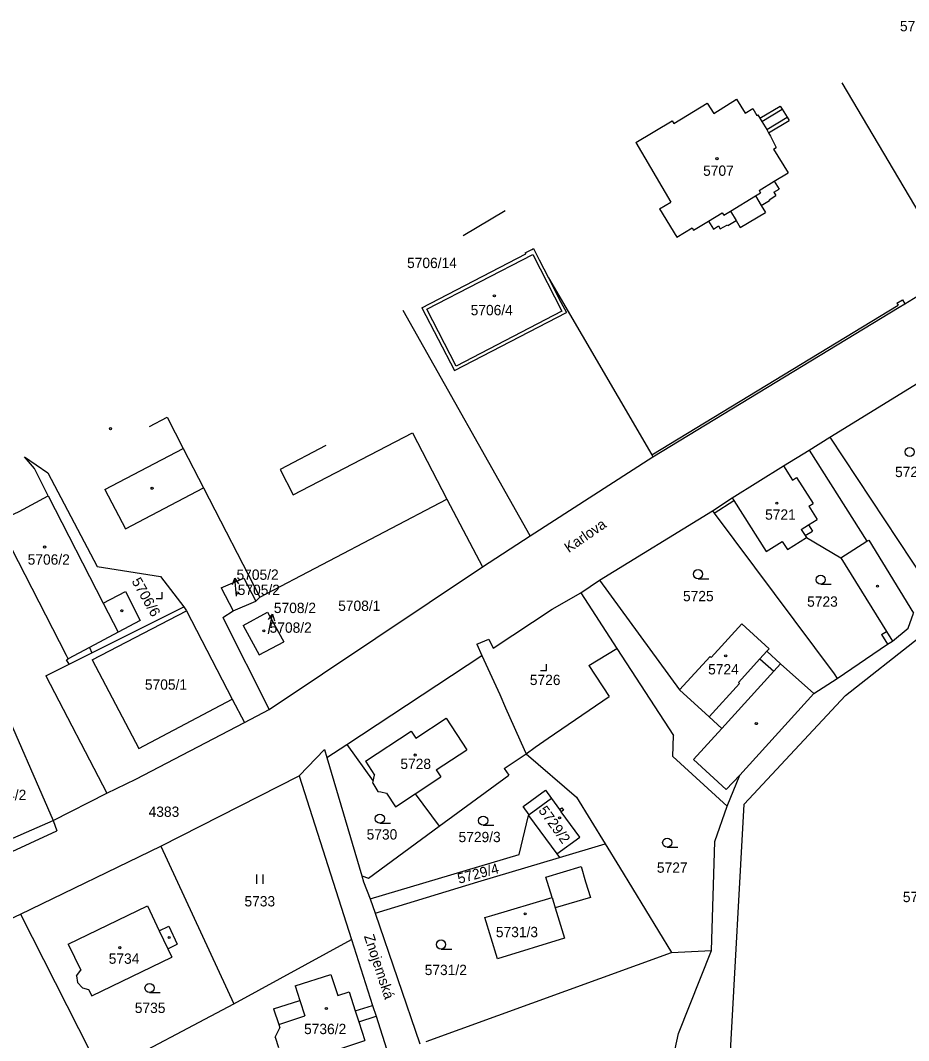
# Model space of a CAD drawing. Extents: x -717507 to -715515, y -957700 to -954941.
# Drawn here: x -716123.2 to -715976.7, y -955263.6 to -955095.4 of the extents above; entities that cross this region are included whole.
import ezdxf

# ---------------------------------------------------------------- set-up
doc = ezdxf.new("R2010")
doc.units = 0
for name, color, linetype in [('Hranice parcel', 7, 'Continuous'), ('Parcelní čísla', 7, 'Continuous'), ('Pop  PČ popisy', 7, 'Continuous'), ('Vnitřní kresba', 7, 'Continuous'), ('Značky budov', 7, 'Continuous'), ('Značky kultur', 7, 'Continuous')]:
    doc.layers.add(name, color=color, linetype=linetype)

msp = doc.modelspace()

# ---------------------------------------------------------------- linework, layer by layer
at = {"layer": 'Hranice parcel'}
for points in [[(-715987.69, -955105.68), (-715972.32, -955131.55)], [(-716008.8, -955110.73), (-716005.06, -955108.37)], [(-716005.06, -955108.37), (-716003.64, -955110.67)], [(-716015.41, -955112.35), (-716009.88, -955109.01)], [(-716009.88, -955109.01), (-716008.8, -955110.73)], [(-716003.64, -955110.67), (-716002.36, -955109.88)], [(-716002.36, -955109.88), (-716001.7, -955111.02)], [(-716001.2, -955111.49), (-715997.86, -955109.49)], [(-715997.86, -955109.49), (-715997.54, -955110)], [(-715997.54, -955110), (-715996.7, -955111.34)], [(-716001.7, -955111.02), (-716001.55, -955110.92)], [(-716001.55, -955110.92), (-716001.2, -955111.49)], [(-715999.76, -955113.88), (-715996.39, -955111.84)], [(-715996.7, -955111.34), (-715996.39, -955111.84)], [(-716021.63, -955115.52), (-716015.66, -955111.92)], [(-716015.66, -955111.92), (-716015.41, -955112.35)], [(-715999.76, -955113.88), (-715999.42, -955114.45)], [(-715999.42, -955114.45), (-715998.49, -955116.34)], [(-716021.63, -955115.52), (-716015.9, -955125.35)], [(-715998.93, -955116.6), (-715998.49, -955116.34)], [(-715998.93, -955116.6), (-715996.55, -955120.52)], [(-715998.82, -955121.89), (-715996.55, -955120.52)], [(-715998.82, -955121.89), (-715998.03, -955123.18)], [(-715998.87, -955123.7), (-715998.03, -955123.18)], [(-716000.97, -955125.87), (-715999.62, -955125.05)], [(-715999.69, -955124.94), (-715998.54, -955124.25)], [(-715999.69, -955124.94), (-715999.62, -955125.05)], [(-715998.87, -955123.7), (-715998.54, -955124.25)], [(-716050.13, -955130.83), (-716043.22, -955126.68)], [(-716017.73, -955126.42), (-716015.9, -955125.35)], [(-716017.73, -955126.42), (-716014.91, -955131.1)], [(-716000.97, -955125.87), (-716000.28, -955127.01)], [(-716012.15, -955129.96), (-716009.65, -955128.46)], [(-716009.65, -955128.46), (-716008.83, -955129.76)], [(-716006.48, -955129.17), (-716005.12, -955128.35)], [(-716005.12, -955128.35), (-716004.43, -955129.49)], [(-716004.43, -955129.49), (-716000.28, -955127.01)], [(-716014.91, -955131.1), (-716012.39, -955129.54)], [(-716012.39, -955129.54), (-716012.15, -955129.96)], [(-716008.83, -955129.76), (-716008.04, -955129.25)], [(-716008.04, -955129.25), (-716007.73, -955129.73)], [(-716007.73, -955129.73), (-716006.55, -955129.06)], [(-716006.55, -955129.06), (-716006.48, -955129.17)], [(-716039.91, -955133.7), (-716038.79, -955133.12)], [(-716039.91, -955133.7), (-716039.82, -955133.87)], [(-716038.79, -955133.12), (-716038.55, -955133)], [(-716038.55, -955133), (-716037.58, -955134.87)], [(-716056.93, -955142.74), (-716039.82, -955133.87)], [(-716037.58, -955134.87), (-716036.07, -955137.79)], [(-716036.07, -955137.79), (-716019.04, -955167.01)], [(-716036.07, -955137.79), (-716034, -955141.8)], [(-715977.3, -955142.09), (-715974.43, -955140.34)], [(-716034, -955141.8), (-716033.1, -955143.53)], [(-715978.21, -955142.64), (-715977.3, -955142.09)], [(-716039.06, -955180.37), (-716060.02, -955143.22)], [(-716056.93, -955142.74), (-716051.56, -955153.11)], [(-716051.56, -955153.11), (-716033.1, -955143.53)], [(-716018.86, -955167.31), (-715978.21, -955142.64)], [(-715989.65, -955164.11), (-715972.95, -955153.83)], [(-715993.06, -955166.21), (-715989.65, -955164.11)], [(-715989.65, -955164.11), (-715973.88, -955187.93)], [(-716120.85, -955169.23), (-716122.47, -955167.34)], [(-716122.47, -955167.34), (-716118.65, -955169.98)], [(-716039.06, -955180.37), (-716018.86, -955167.31)], [(-716019.04, -955167.01), (-716018.86, -955167.31)], [(-715997.31, -955168.83), (-715993.06, -955166.21)], [(-716005.75, -955174.07), (-715997.31, -955168.83)], [(-716118.59, -955173.74), (-716120.85, -955169.23)], [(-716118.65, -955169.98), (-716110.5, -955185.44)], [(-716126.97, -955178), (-716123.36, -955176.36), (-716118.59, -955173.74)], [(-716118.59, -955173.74), (-716109.53, -955191.45)], [(-716008.99, -955176.24), (-716005.75, -955174.07)], [(-716005.75, -955174.07), (-716005.48, -955174.51)], [(-716083.7, -955190.49), (-716052.81, -955174.31)], [(-716052.81, -955174.31), (-716046.97, -955185.48)], [(-716005.48, -955174.51), (-716000.17, -955182.94)], [(-716027.64, -955187.66), (-716008.99, -955176.24)], [(-716008.99, -955176.24), (-716008.72, -955176.6)], [(-716008.72, -955176.6), (-715988.93, -955203.13)], [(-716115.27, -955200.63), (-716115.56, -955200.09), (-716126.97, -955178)], [(-716046.97, -955185.48), (-716039.06, -955180.37)], [(-715996.66, -955182.61), (-715993.51, -955180.65)], [(-715993.51, -955180.65), (-715987.84, -955183.98)], [(-716000.17, -955182.94), (-715997.5, -955181.27)], [(-715997.5, -955181.27), (-715996.66, -955182.61)], [(-715987.84, -955183.98), (-715980.3, -955196.11)], [(-716110.5, -955185.44), (-716100.06, -955187.09)], [(-716082.16, -955209.02), (-716046.97, -955185.48)], [(-716100.06, -955187.09), (-716096.2, -955192.09)], [(-716090.05, -955188.92), (-716086.33, -955187.35)], [(-716086.33, -955187.35), (-716084.35, -955191.14)], [(-716090.05, -955188.92), (-716088.05, -955192.75)], [(-716030.73, -955189.77), (-716027.64, -955187.66)], [(-716027.64, -955187.66), (-716014.46, -955205.75)], [(-716109.53, -955191.45), (-716105.82, -955189.55), (-716103.41, -955194.34), (-716107.07, -955196.25)], [(-716084.35, -955191.14), (-716083.7, -955190.49)], [(-716035.48, -955192.46), (-716030.73, -955189.77)], [(-716030.73, -955189.77), (-716024.77, -955198.93)], [(-716111.37, -955199.63), (-716096.2, -955192.09)], [(-716096.2, -955192.09), (-716095.75, -955192.74)], [(-716088.05, -955192.75), (-716084.35, -955191.14)], [(-716045.19, -955198.88), (-716035.48, -955192.46)], [(-716095.75, -955192.74), (-716088.23, -955207.29)], [(-716089.76, -955193.81), (-716088.05, -955192.75)], [(-716089.76, -955193.81), (-716082.16, -955209.02)], [(-716086.41, -955195.12), (-716082.39, -955192.95)], [(-716082.39, -955192.95), (-716079.74, -955197.82)], [(-715976.75, -955195.61), (-715975.85, -955193.1)], [(-716086.41, -955195.12), (-716083.78, -955200)], [(-716009.23, -955200.42), (-716004.16, -955194.89)], [(-716004.16, -955194.89), (-715999.69, -955198.98)], [(-715979.32, -955197.7), (-715976.75, -955195.61)], [(-716107.07, -955196.25), (-716111.77, -955198.76)], [(-716047.89, -955198.2), (-716045.88, -955197.4)], [(-716045.88, -955197.4), (-716045.19, -955198.88)], [(-715987.09, -955206.67), (-715974.9, -955197.11)], [(-715981.14, -955196.63), (-715980.3, -955196.11)], [(-715981.14, -955196.63), (-715980.17, -955198.23)], [(-716111.77, -955198.76), (-716111.37, -955199.63)], [(-716083.78, -955200), (-716079.74, -955197.82)], [(-716047.89, -955198.2), (-716047.03, -955200.09)], [(-716029.43, -955201.72), (-716024.77, -955198.93)], [(-716024.77, -955198.93), (-716015.42, -955213.31)], [(-716000.06, -955199.39), (-715999.69, -955198.98)], [(-715988.45, -955203.88), (-715980.17, -955198.23)], [(-715980.17, -955198.23), (-715979.32, -955197.7)], [(-716115.14, -955201.51), (-716115.56, -955200.79), (-716115.27, -955200.63)], [(-716115.14, -955201.51), (-716111.37, -955199.63)], [(-716069.3, -955214.76), (-716047.03, -955200.09)], [(-716047.03, -955200.09), (-716044.1, -955206.54), (-716043.13, -955208.71), (-716040.06, -955215.58), (-716039.75, -955216.28)], [(-716014.46, -955205.75), (-716009.42, -955200.26)], [(-716009.42, -955200.26), (-716009.23, -955200.42)], [(-716000.06, -955199.39), (-715997.78, -955201.44)], [(-716118.98, -955203.42), (-716115.14, -955201.51)], [(-716029.43, -955201.72), (-716026.06, -955206.87)], [(-715997.78, -955201.44), (-715992.32, -955206.35)], [(-716118.98, -955203.42), (-716108.91, -955222.79)], [(-715992.32, -955206.35), (-715988.45, -955203.88)], [(-715988.93, -955203.13), (-715988.45, -955203.88)], [(-716126.78, -955206.75), (-716117.79, -955227.32)], [(-716088.23, -955207.29), (-716086.22, -955211.13)], [(-716036.1, -955213.7), (-716026.06, -955206.87)], [(-716004.49, -955219.83), (-715992.32, -955206.35)], [(-716003.78, -955224.58), (-715987.09, -955206.67)], [(-716086.22, -955211.13), (-716082.16, -955209.02)], [(-716104.15, -955220.46), (-716086.22, -955211.13)], [(-716038.28, -955215.18), (-716036.1, -955213.7)], [(-716015.54, -955216.77), (-716015.42, -955213.31)], [(-716077.16, -955219.93), (-716072.99, -955215.59)], [(-716072.99, -955215.59), (-716072.6, -955216.93)], [(-716072.6, -955216.93), (-716069.3, -955214.76)], [(-716069.3, -955214.76), (-716064.99, -955220.82)], [(-716039.75, -955216.28), (-716038.28, -955215.18)], [(-716072.6, -955216.93), (-716066.86, -955236.41)], [(-716043.36, -955218.75), (-716039.75, -955216.28)], [(-716039.75, -955216.28), (-716031.42, -955223.44)], [(-716015.54, -955216.77), (-716006.58, -955224.96)], [(-716043.36, -955218.75), (-716042.6, -955219.81)], [(-716108.91, -955222.79), (-716104.15, -955220.46)], [(-716100.02, -955231.55), (-716077.16, -955219.93)], [(-716077.16, -955219.93), (-716068.57, -955246.93)], [(-716065.06, -955221.15), (-716064.99, -955220.82)], [(-716065.06, -955221.15), (-716064.2, -955222.49)], [(-716054.11, -955228.24), (-716042.6, -955219.81)], [(-716006.58, -955224.96), (-716004.49, -955219.83)], [(-716117.79, -955227.32), (-716108.91, -955222.79)], [(-716064.2, -955222.49), (-716063.73, -955222.59)], [(-716063.73, -955222.59), (-716062.8, -955222.79)], [(-716062.8, -955222.79), (-716061.3, -955225.02)], [(-716061.3, -955225.02), (-716058.04, -955222.88)], [(-716058.04, -955222.88), (-716054.11, -955228.24)], [(-716040.25, -955225), (-716036.58, -955222.28)], [(-716036.58, -955222.28), (-716035.56, -955223.68)], [(-716035.56, -955223.68), (-716034.25, -955225.48)], [(-716031.42, -955223.44), (-716026.72, -955231.13)], [(-716039.24, -955226.38), (-716040.25, -955225)], [(-716034.25, -955225.48), (-716033.88, -955225.2)], [(-716033.58, -955225.59), (-716033.97, -955225.87)], [(-716030.92, -955230.05), (-716033.97, -955225.87)], [(-716033.88, -955225.2), (-716033.58, -955225.59)], [(-716008.64, -955230.76), (-716006.58, -955224.96)], [(-716006.06, -955265.38), (-716003.78, -955224.58)], [(-716127.97, -955231.77), (-716117.79, -955227.32)], [(-716040.91, -955232.9), (-716039.35, -955226.46)], [(-716039.24, -955226.38), (-716039.35, -955226.46)], [(-716039.35, -955226.46), (-716034.7, -955232.81)], [(-716065.73, -955236.8), (-716054.11, -955228.24)], [(-716034.7, -955232.81), (-716030.92, -955230.05)], [(-716034.25, -955233.38), (-716026.72, -955231.13)], [(-716026.72, -955231.13), (-716024.35, -955235)], [(-716009.2, -955248.72), (-716008.64, -955230.76)], [(-716123.16, -955242.77), (-716100.02, -955231.55)], [(-716100.02, -955231.55), (-716087.98, -955257.52)], [(-716065.45, -955240.2), (-716040.91, -955232.9)], [(-716034.7, -955232.81), (-716034.25, -955233.38)], [(-716047.69, -955237.41), (-716034.25, -955233.38)], [(-716036.48, -955236.62), (-716030.69, -955234.88)], [(-716030.69, -955234.88), (-716029.94, -955237.39)], [(-716024.35, -955235), (-716015.77, -955249.05)], [(-716066.86, -955236.41), (-716065.73, -955236.8)], [(-716066.86, -955236.41), (-716066.57, -955237.42)], [(-716066.57, -955237.42), (-716065.45, -955240.2)], [(-716064.64, -955242.58), (-716047.69, -955237.41)], [(-716035.47, -955239.97), (-716036.48, -955236.62)], [(-716029.94, -955237.39), (-716029.16, -955240.01)], [(-716115.31, -955247.68), (-716102.2, -955241.38)], [(-716102.2, -955241.38), (-716100.26, -955245.47)], [(-716065.45, -955240.2), (-716064.64, -955242.58)], [(-716045.4, -955242.97), (-716035.47, -955239.97)], [(-716029.16, -955240.01), (-716034.94, -955241.72)], [(-716134.57, -955248.07), (-716123.16, -955242.77)], [(-716123.16, -955242.77), (-716109.77, -955269.05)], [(-716064.64, -955242.58), (-716057.29, -955264.13)], [(-716046.55, -955243.32), (-716045.4, -955242.97)], [(-716034.94, -955241.72), (-716033.43, -955246.7)], [(-716100.26, -955245.47), (-716098.71, -955244.74)], [(-716098.71, -955244.74), (-716097.3, -955247.7)], [(-716044.48, -955250.09), (-716046.55, -955243.32)], [(-716115.31, -955247.68), (-716113.21, -955251.97)], [(-716098.85, -955248.44), (-716097.3, -955247.7)], [(-716087.98, -955257.52), (-716068.57, -955246.93)], [(-716068.57, -955246.93), (-716065.08, -955257.78)], [(-716033.43, -955246.7), (-716044.48, -955250.09)], [(-716098.85, -955248.44), (-716098.18, -955249.85)], [(-716056.26, -955263.75), (-716015.77, -955249.05)], [(-716015.77, -955249.05), (-716009.2, -955248.72)], [(-716014.63, -955262.44), (-716009.2, -955248.72)], [(-716111.4, -955256.21), (-716098.18, -955249.85)], [(-716113.94, -955252.9), (-716113.21, -955251.97)], [(-716113.94, -955252.9), (-716113.75, -955254.04)], [(-716077.86, -955254.56), (-716071.95, -955252.69)], [(-716071.95, -955252.69), (-716070.83, -955256.17)], [(-716113.75, -955254.04), (-716112.94, -955254.87)], [(-716077.86, -955254.56), (-716077.08, -955256.97)], [(-716112.94, -955254.87), (-716111.92, -955255.15)], [(-716111.92, -955255.15), (-716111.4, -955256.21)], [(-716070.83, -955256.17), (-716068.93, -955255.58)], [(-716068.93, -955255.58), (-716067.93, -955258.67)], [(-716109.77, -955269.05), (-716087.98, -955257.52)], [(-716081.42, -955258.37), (-716077.08, -955256.97)], [(-716067.93, -955258.67), (-716065.08, -955257.78)], [(-716065.08, -955257.78), (-716064.5, -955259.59)], [(-716081.42, -955258.37), (-716080.55, -955260.93)], [(-716067.33, -955260.51), (-716064.5, -955259.59)], [(-716064.5, -955259.59), (-716062.44, -955266)], [(-716081.13, -955263.04), (-716080.4, -955261.49)], [(-716080.55, -955260.93), (-716080.4, -955261.49)], [(-716067.33, -955260.51), (-716066.33, -955263.59)], [(-716081.13, -955263.04), (-716080.6, -955264.71)], [(-716021.47, -955293.97), (-716014.63, -955262.44)], [(-716070.14, -955264.86), (-716066.33, -955263.59)]]:
    msp.add_lwpolyline(points, dxfattribs=at)
at = {"layer": 'Pop  PČ popisy'}
for points in [[(-716088.19, -955188.36), (-716087.78, -955187.32), (-716087.2, -955188.27)], [(-716087.52, -955190.31), (-716087.78, -955187.32)], [(-716082.26, -955194.16), (-716081.56, -955193.29), (-716081.28, -955194.37)], [(-716082.19, -955196.22), (-716081.56, -955193.29)], [(-716082.26, -955196.54), (-716082.19, -955196.22)]]:
    msp.add_lwpolyline(points, dxfattribs=at)
at = {"layer": 'Vnitřní kresba'}
for points in [[(-716000.89, -955112.01), (-715997.54, -955110)], [(-716001.2, -955111.49), (-716000.89, -955112.01)], [(-716000.07, -955113.37), (-715996.7, -955111.34)], [(-716000.89, -955112.01), (-716000.07, -955113.37)], [(-716000.07, -955113.37), (-715999.76, -955113.88)], [(-716001.33, -955123.41), (-715998.82, -955121.89)], [(-716001.33, -955123.41), (-716001.08, -955123.82)], [(-716006.06, -955126.81), (-716001.91, -955124.31)], [(-716001.91, -955124.31), (-716001.08, -955123.82)], [(-716001.91, -955124.31), (-716000.97, -955125.87)], [(-716007.14, -955127.5), (-716006.06, -955126.81)], [(-716006.06, -955126.81), (-716005.12, -955128.35)], [(-716009.65, -955128.46), (-716007.39, -955127.09)], [(-716007.39, -955127.09), (-716007.14, -955127.5)], [(-716056.13, -955142.99), (-716038.66, -955133.95)], [(-716038.66, -955133.95), (-716033.86, -955143.32)], [(-715978.6, -955141.99), (-715977.69, -955141.44)], [(-715978.6, -955141.99), (-715978.39, -955142.34)], [(-715977.69, -955141.44), (-715977.3, -955142.09)], [(-716051.27, -955152.36), (-716056.13, -955142.99)], [(-716033.86, -955143.32), (-716051.27, -955152.36)], [(-716019.04, -955167.01), (-715978.39, -955142.34)], [(-716101.88, -955162.32), (-716098.97, -955160.81)], [(-716098.97, -955160.81), (-716096.31, -955165.94)], [(-716078.16, -955173.6), (-716058.49, -955163.36)], [(-716058.49, -955163.36), (-716052.81, -955174.31)], [(-716072.81, -955165.44), (-716080.34, -955169.42)], [(-716109.22, -955172.73), (-716096.31, -955165.94)], [(-716096.31, -955165.94), (-716092.94, -955172.42)], [(-715993.06, -955166.21), (-715983.57, -955181.25)], [(-715997.31, -955168.83), (-715995.81, -955171.19)], [(-716080.34, -955169.42), (-716078.16, -955173.6)], [(-716105.84, -955179.21), (-716092.94, -955172.42)], [(-716092.94, -955172.42), (-716083.7, -955190.49)], [(-715995.81, -955171.19), (-715995.13, -955170.76)], [(-715995.13, -955170.76), (-715992.42, -955175.02)], [(-716109.22, -955172.73), (-716105.84, -955179.21)], [(-716008.72, -955176.6), (-716005.48, -955174.51)], [(-715993.13, -955175.46), (-715992.42, -955175.02)], [(-715993.13, -955175.46), (-715991.75, -955177.67)], [(-715994.36, -955179.3), (-715993.16, -955178.55)], [(-715993.16, -955178.55), (-715991.75, -955177.67)], [(-715993.16, -955178.55), (-715992.52, -955179.56)], [(-715994.36, -955179.3), (-715993.72, -955180.31)], [(-715993.72, -955180.31), (-715992.52, -955179.56)], [(-715993.72, -955180.31), (-715993.51, -955180.65)], [(-715987.84, -955183.98), (-715983.57, -955181.25)], [(-715983.57, -955181.25), (-715983.25, -955181.05)], [(-715983.25, -955181.05), (-715975.85, -955193.1)], [(-716109.53, -955191.45), (-716107.07, -955196.25)], [(-716111.31, -955200.78), (-716095.75, -955192.74)], [(-715980.3, -955196.11), (-715979.32, -955197.7)], [(-716111.77, -955198.76), (-716115.27, -955200.63)], [(-716111.31, -955200.78), (-716103.66, -955215.41)], [(-716004.74, -955204.55), (-716001.2, -955200.65)], [(-716001.2, -955200.65), (-716000.06, -955199.39)], [(-716001.2, -955200.65), (-715998.92, -955202.69)], [(-716007.49, -955212.11), (-715998.92, -955202.69)], [(-715998.92, -955202.69), (-715997.78, -955201.44)], [(-716014.46, -955205.75), (-716009.56, -955210.22)], [(-716009.56, -955210.22), (-716004.56, -955204.71)], [(-716004.74, -955204.55), (-716004.56, -955204.71)], [(-716103.66, -955215.41), (-716088.23, -955207.29)], [(-716057.97, -955213.73), (-716052.95, -955210.45)], [(-716052.95, -955210.45), (-716049.54, -955215.63)], [(-716009.56, -955210.22), (-716007.49, -955212.11)], [(-716066.26, -955217.51), (-716058.74, -955212.57)], [(-716058.74, -955212.57), (-716057.97, -955213.73)], [(-716012.17, -955217.26), (-716007.49, -955212.11)], [(-716054.57, -955218.92), (-716049.54, -955215.63)], [(-716066.26, -955217.51), (-716064.77, -955219.8)], [(-716012.17, -955217.26), (-716006.74, -955222.17)], [(-716054.57, -955218.92), (-716053.8, -955220.09)], [(-716064.99, -955220.82), (-716064.77, -955219.8)], [(-716058.04, -955222.88), (-716053.8, -955220.09)], [(-716006.74, -955222.17), (-716004.49, -955219.83)], [(-716035.56, -955223.68), (-716039.24, -955226.38)], [(-716034.25, -955225.48), (-716033.97, -955225.87)], [(-716117.79, -955227.32), (-716117.16, -955229)], [(-716148, -955243.26), (-716117.16, -955229)], [(-716035.47, -955239.97), (-716034.94, -955241.72)], [(-716100.26, -955245.47), (-716098.85, -955248.44)], [(-716077.08, -955256.97), (-716076.27, -955259.49)], [(-716080.55, -955260.93), (-716076.27, -955259.49)], [(-716067.93, -955258.67), (-716067.33, -955260.51)]]:
    msp.add_lwpolyline(points, dxfattribs=at)
at = {"layer": 'Značky budov'}
for centre in [(-716008.27, -955118.16), (-716044.99, -955140.77), (-716108.3, -955162.68), (-716101.45, -955172.51), (-715998.41, -955174.97), (-716119.17, -955182.2), (-715981.79, -955188.67), (-716087.35, -955189.78), (-716106.45, -955192.71), (-716083.01, -955196.01), (-716006.83, -955200.15), (-716001.78, -955211.32), (-716058.06, -955216.5), (-716034.23, -955226.86), (-716039.92, -955242.7), (-716098.63, -955246.59), (-716106.77, -955248.28), (-716072.7, -955258.3)]:
    msp.add_circle(centre, 0.175, dxfattribs=at)
at = {"layer": 'Značky kultur'}
for points in [[(-716011.39, -955187.43), (-716009.64, -955187.43)], [(-715991.16, -955188.34), (-715989.41, -955188.34)], [(-716100.78, -955190.67), (-716099.78, -955190.67), (-716099.78, -955189.67)], [(-716037.37, -955202.54), (-716036.37, -955202.54), (-716036.37, -955201.54)], [(-716063.88, -955227.74), (-716062.13, -955227.74)], [(-716046.84, -955228.07), (-716045.09, -955228.07)], [(-716016.48, -955231.69), (-716014.73, -955231.69)], [(-716084.17, -955237.73), (-716084.17, -955236.23)], [(-716083.13, -955237.73), (-716083.13, -955236.23)], [(-716053.78, -955248.5), (-716052.03, -955248.5)], [(-716101.87, -955255.66), (-716100.12, -955255.66)]]:
    msp.add_lwpolyline(points, dxfattribs=at)
for centre in [(-715976.48, -955166.53), (-716011.39, -955186.68), (-715991.16, -955187.59), (-716063.88, -955226.99), (-716046.84, -955227.32), (-716016.48, -955230.94), (-716053.78, -955247.75), (-716101.87, -955254.91)]:
    msp.add_circle(centre, 0.75, dxfattribs=at)

# ---------------------------------------------------------------- texts
at = {"layer": 'Parcelní čísla'}
for s, p in [('5714/1', (-715978.09, -955097.15)), ('5707', (-716010.56, -955120.99)), ('5706/14', (-716059.39, -955136.2)), ('5706/4', (-716048.9, -955143.98)), ('5722', (-715978.9, -955170.67)), ('5721', (-716000.33, -955177.7)), ('5706/2', (-716121.97, -955185.11)), ('5705/2', (-716087.52, -955187.61)), ('5705/2', (-716087.32, -955190.11)), ('5725', (-716013.88, -955191.14)), ('5723', (-715993.4, -955192.05)), ('5708/2', (-716081.36, -955193.09)), ('5708/1', (-716070.75, -955192.74)), ('5708/2', (-716082.06, -955196.34)), ('5724', (-716009.73, -955203.21)), ('5705/1', (-716102.63, -955205.73)), ('5726', (-716039.14, -955204.96)), ('5728', (-716060.49, -955218.81)), ('5704/2', (-716129.15, -955223.93)), ('4383', (-716102.02, -955226.7)), ('5730', (-716066.06, -955230.44)), ('5729/3', (-716050.9, -955230.87)), ('5727', (-716018.18, -955235.92)), ('5765', (-715977.61, -955240.76)), ('5733', (-716086.21, -955241.47)), ('5731/3', (-716044.74, -955246.54)), ('5734', (-716108.6, -955250.93)), ('5731/2', (-716056.48, -955252.79)), ('5735', (-716104.3, -955259.04)), ('5736/2', (-716076.38, -955262.53))]:
    msp.add_text(s, height=1.7, dxfattribs=at).set_placement(p)
for s, rotation, p in [('5706/6', 299.5024, (-716104.88, -955187.83)), ('5729/2', 305.9024, (-716037.8, -955225.66)), ('5729/4', 15.0001, (-716050.82, -955237.75))]:
    msp.add_text(s, height=1.7, rotation=rotation, dxfattribs=at).set_placement(p)
at = {"layer": 'Pop  PČ popisy'}
for s, rotation, p in [('Karlova', 34.7003, (-716032.71, -955183.22)), ('Znojemská', 288.3023, (-716066.53, -955246.38))]:
    msp.add_text(s, height=1.7, rotation=rotation, dxfattribs=at).set_placement(p)

doc.saveas('drawing.dxf')
